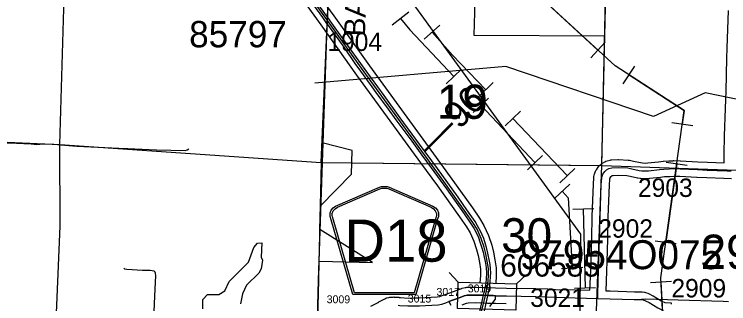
# Model space of a CAD drawing. Extents: x -157.2 to -99.3, y 12.2 to 46.2.
# Drawn here: x -145.747 to -143.029, y 36.628 to 37.727 of the extents above; entities that cross this region are included whole.
import ezdxf

# ---------------------------------------------------------------- set-up
doc = ezdxf.new("R2010")
doc.units = 0
for name, color, linetype in [('tdCoCityStreetMinor', 7, 'Continuous'), ('tdCoCorpBndry', 7, 'Continuous'), ('tdCoCorpPopTxt', 7, 'Continuous'), ('tdCoDivCarto', 7, 'Continuous'), ('tdCoHydroRiver', 7, 'Continuous'), ('tdCoPipe', 7, 'Continuous'), ('tdCoPipe1', 7, 'Continuous'), ('tdCoPipe2', 7, 'Continuous'), ('tdCoPriCL', 7, 'Continuous'), ('tdCoPriDiv', 7, 'Continuous'), ('tdCoSecRdNmbr', 7, 'Continuous'), ('tdCoSecRdTxt', 7, 'Continuous'), ('tdCoSecRteBand', 7, 'Continuous'), ('tdCoSecRteCL', 7, 'Continuous'), ('tdCoSectLine', 7, 'Continuous'), ('tdCoSectLinePart', 7, 'Continuous'), ('tdCoSectNmbr', 7, 'Continuous'), ('tdCoShieldCoRteHrd', 7, 'Continuous'), ('tdCoStrucNonDivPri', 7, 'Continuous'), ('tdCoStrucPriMaintName', 7, 'Continuous'), ('tdCoStrucSecFHWANum', 7, 'Continuous'), ('tdCoSurfAsphalt', 7, 'Continuous'), ('tdCoSurfGravel', 7, 'Continuous'), ('tdCoSurfLNO', 7, 'Continuous'), ('tdCoTwpBndry', 7, 'Continuous'), ('tdStHwyPriRefPost1', 7, 'Continuous')]:
    doc.layers.add(name, color=color, linetype=linetype)

msp = doc.modelspace()

# ---------------------------------------------------------------- linework, layer by layer
at = {"layer": 'tdCoCityStreetMinor'}
for points in [[(-146.0712, 37.2523), (-146.0597, 37.253), (-146.0068, 37.2504), (-145.9695, 37.2485), (-145.8817, 37.2441), (-145.8233, 37.2411), (-145.8193, 37.2409), (-145.7377, 37.2377), (-145.6822, 37.2347), (-145.6612, 37.2332), (-145.6373, 37.2347), (-145.5966, 37.2335), (-145.5697, 37.232), (-145.5083, 37.2261), (-145.4028, 37.2217), (-145.3228, 37.2181)], [(-145.3228, 37.2181), (-145.3152, 37.2177), (-145.2062, 37.2125), (-145.0957, 37.2106), (-145.0888, 37.2125), (-145.0827, 37.2162)], [(-145.3295, 36.7634), (-145.3271, 36.7609), (-145.3192, 36.7589), (-145.2587, 36.7552), (-145.2301, 36.7555), (-145.2225, 36.7545), (-145.2163, 36.7528), (-145.2119, 36.7491), (-145.2114, 36.7479)], [(-145.2263, 36.2821), (-145.2252, 36.3091), (-145.223, 36.3986), (-145.2205, 36.4882), (-145.2173, 36.5417), (-145.2102, 36.6845), (-145.2084, 36.734), (-145.2094, 36.7434), (-145.2114, 36.7479)]]:
    msp.add_lwpolyline(points, dxfattribs=at)
at = {"layer": 'tdCoCorpBndry'}
for points in [[(-143.9908, 37.9076), (-143.9989, 37.6487), (-143.5002, 37.6452), (-143.4894, 38.1369)], [(-144.5957, 36.4338), (-144.5873, 36.79), (-144.3834, 36.7845), (-144.5845, 36.9098), (-144.5823, 37), (-144.4643, 37.1202), (-144.4611, 37.2101), (-144.5753, 37.2385), (-144.5551, 37.7042), (-144.5517, 37.7829)], [(-143.9379, 36.6172), (-143.9166, 36.6446), (-143.9163, 36.6584), (-143.925, 36.6586), (-143.9455, 36.6591), (-143.9537, 36.6594), (-143.9628, 36.6598), (-143.9823, 36.6603), (-143.9909, 36.6606), (-144.0242, 36.6601), (-144.0353, 36.6574), (-144.0548, 36.65), (-144.0932, 36.6357), (-144.0861, 36.6222)]]:
    msp.add_lwpolyline(points, dxfattribs=at)
at = {"layer": 'tdCoDivCarto'}
for points in [[(-144.5549, 37.7164), (-144.5986, 37.7758), (-144.6594, 37.8612)], [(-144.5549, 37.7164), (-144.5986, 37.7758), (-144.6594, 37.8612)], [(-144.6082, 37.7617), (-144.5743, 37.715), (-144.5559, 37.6892)], [(-144.6082, 37.7617), (-144.5743, 37.715), (-144.5559, 37.6892)], [(-144.5545, 37.7158), (-144.5549, 37.7164)], [(-144.5545, 37.7158), (-144.5549, 37.7164)], [(-143.9455, 36.6591), (-143.9408, 36.681), (-143.9377, 36.6975), (-143.9358, 36.7109), (-143.9346, 36.7312), (-143.9343, 36.7451), (-143.9348, 36.7602), (-143.937, 36.7771), (-143.9386, 36.7896), (-143.9449, 36.8204), (-143.9501, 36.8419), (-143.9537, 36.8536), (-143.9609, 36.8758), (-143.9731, 36.9031), (-143.9841, 36.9239), (-143.9941, 36.9401), (-144.0252, 36.9846), (-144.0584, 37.0327), (-144.1368, 37.1414), (-144.2056, 37.2342), (-144.2788, 37.3336), (-144.3397, 37.4192), (-144.4117, 37.5172), (-144.4774, 37.6095), (-144.5322, 37.6855), (-144.5545, 37.7158)], [(-143.9455, 36.6591), (-143.9408, 36.681), (-143.9377, 36.6975), (-143.9358, 36.7109), (-143.9346, 36.7312), (-143.9343, 36.7451), (-143.9348, 36.7602), (-143.937, 36.7771), (-143.9386, 36.7896), (-143.9449, 36.8204), (-143.9501, 36.8419), (-143.9537, 36.8536), (-143.9609, 36.8758), (-143.9731, 36.9031), (-143.9841, 36.9239), (-143.9941, 36.9401), (-144.0252, 36.9846), (-144.0584, 37.0327), (-144.1368, 37.1414), (-144.2056, 37.2342), (-144.2788, 37.3336), (-144.3397, 37.4192), (-144.4117, 37.5172), (-144.4774, 37.6095), (-144.5322, 37.6855), (-144.5545, 37.7158)], [(-144.5559, 37.6892), (-144.5556, 37.6889)], [(-144.5559, 37.6892), (-144.5556, 37.6889)], [(-144.5556, 37.6889), (-144.4937, 37.6023), (-144.4508, 37.5411), (-144.4293, 37.5115), (-144.3862, 37.4516), (-144.3711, 37.4309), (-144.3247, 37.3675), (-144.2954, 37.3268), (-144.235, 37.2452), (-144.196, 37.1917), (-144.1605, 37.1438), (-144.103, 37.0644), (-144.0352, 36.9692), (-144.0113, 36.9345), (-143.999, 36.9147), (-143.9926, 36.9029), (-143.9812, 36.8792), (-143.9751, 36.8634), (-143.9677, 36.8403), (-143.963, 36.824), (-143.9588, 36.8045), (-143.9556, 36.7882), (-143.9521, 36.765), (-143.9506, 36.7443), (-143.9514, 36.7239), (-143.9534, 36.7054), (-143.9595, 36.6753), (-143.9628, 36.6598)], [(-144.5556, 37.6889), (-144.4937, 37.6023), (-144.4508, 37.5411), (-144.4293, 37.5115), (-144.3862, 37.4516), (-144.3711, 37.4309), (-144.3247, 37.3675), (-144.2954, 37.3268), (-144.235, 37.2452), (-144.196, 37.1917), (-144.1605, 37.1438), (-144.103, 37.0644), (-144.0352, 36.9692), (-144.0113, 36.9345), (-143.999, 36.9147), (-143.9926, 36.9029), (-143.9812, 36.8792), (-143.9751, 36.8634), (-143.9677, 36.8403), (-143.963, 36.824), (-143.9588, 36.8045), (-143.9556, 36.7882), (-143.9521, 36.765), (-143.9506, 36.7443), (-143.9514, 36.7239), (-143.9534, 36.7054), (-143.9595, 36.6753), (-143.9628, 36.6598)], [(-143.9628, 36.6598), (-143.9726, 36.6144), (-143.9847, 36.5638), (-144.017, 36.4363), (-144.0481, 36.3133), (-144.0702, 36.238), (-144.0804, 36.1973), (-144.0881, 36.1648), (-144.0882, 36.1644)], [(-143.9628, 36.6598), (-143.9726, 36.6144), (-143.9847, 36.5638), (-144.017, 36.4363), (-144.0481, 36.3133), (-144.0702, 36.238), (-144.0804, 36.1973), (-144.0881, 36.1648), (-144.0882, 36.1644)], [(-144.0708, 36.1641), (-144.0627, 36.1994), (-144.0584, 36.2166), (-144.0441, 36.2673), (-144.0204, 36.3555), (-143.9898, 36.4757), (-143.9721, 36.5448), (-143.957, 36.6062), (-143.9532, 36.6232), (-143.9482, 36.6464), (-143.9455, 36.6591)], [(-144.0708, 36.1641), (-144.0627, 36.1994), (-144.0584, 36.2166), (-144.0441, 36.2673), (-144.0204, 36.3555), (-143.9898, 36.4757), (-143.9721, 36.5448), (-143.957, 36.6062), (-143.9532, 36.6232), (-143.9482, 36.6464), (-143.9455, 36.6591)]]:
    msp.add_lwpolyline(points, dxfattribs=at)
at = {"layer": 'tdCoHydroRiver'}
msp.add_lwpolyline([(-145.0289, 36.6078), (-145.0293, 36.6442), (-145.0114, 36.6625), (-144.9687, 36.6627), (-144.9462, 36.6762), (-144.9292, 36.7119), (-144.8558, 36.7853), (-144.835, 36.8415), (-144.8219, 36.8584), (-144.8045, 36.8594), (-144.8078, 36.8043), (-144.8019, 36.793), (-144.8077, 36.7601), (-144.8161, 36.7445), (-144.8634, 36.6987), (-144.8787, 36.666), (-144.8862, 36.6268)], dxfattribs=at)
at = {"layer": 'tdCoPipe'}
for p, q in [((-143.5538, 37.5619), (-143.4992, 37.6212)), ((-143.43, 37.4632), (-143.3862, 37.5307)), ((-143.2456, 37.3161), (-143.1658, 37.3049)), ((-143.2667, 37.1655), (-143.1871, 37.1543)), ((-143.3086, 36.8674), (-143.2288, 36.8562)), ((-143.3271, 36.709), (-143.2468, 36.7133))]:
    msp.add_line(p, q, dxfattribs=at)
for points in [[(-143.6986, 32.0013), (-143.8537, 32.158), (-143.9767, 32.8002), (-143.9699, 34.5789), (-143.6225, 35.3891), (-143.4712, 35.4798), (-143.4387, 35.9175), (-143.2567, 36.1488), (-143.2877, 36.7262), (-143.1986, 37.3614), (-143.4614, 37.5316), (-143.9241, 37.9577), (-144.2011, 38.3657), (-144.4708, 38.931)], [(-144.5317, 38.1832), (-143.5928, 36.8918), (-143.6099, 34.8602), (-143.4402, 34.5415), (-143.5694, 34.3304), (-143.5634, 33.7239), (-143.4667, 33.4993), (-143.5656, 33.4168), (-143.4755, 33.1706), (-143.455, 32.2186), (-143.5122, 31.3968), (-143.6938, 30.9939), (-143.6811, 29.9265), (-143.7347, 27.6406), (-143.7362, 26.8708), (-143.9217, 26.7732), (-143.8183, 26.5085), (-143.8116, 26.1034), (-144.0839, 25.9289), (-143.0557, 24.1836)], [(-143.7479, 37.7954), (-143.5265, 37.5915)], [(-141.4768, 37.6316), (-142.3456, 37.409), (-142.8158, 37.3667), (-143.1182, 37.4285), (-143.3155, 37.3393), (-143.8762, 37.5293), (-144.6035, 37.4656)], [(-143.4081, 37.497), (-143.1986, 37.3614), (-143.2057, 37.3105)], [(-143.2269, 37.1599), (-143.2687, 36.8618)], [(-143.2869, 36.7112), (-143.2708, 36.4106)]]:
    msp.add_lwpolyline(points, dxfattribs=at)
at = {"layer": 'tdCoPipe1'}
for p, q in [((-144.1873, 37.6336), (-144.1274, 37.6868)), ((-143.9824, 37.4126), (-143.9244, 37.4679)), ((-143.879, 37.304), (-143.8209, 37.3593)), ((-143.672, 37.0868), (-143.614, 37.1422)), ((-143.6225, 36.9871), (-143.5424, 36.989)), ((-143.6154, 36.6872), (-143.5352, 36.6891))]:
    msp.add_line(p, q, dxfattribs=at)
for points in [[(-144.1574, 37.6602), (-144.0792, 37.5723), (-143.9534, 37.4403)], [(-143.8499, 37.3317), (-143.643, 37.1145)], [(-143.5825, 36.9881), (-143.5753, 36.6882)]]:
    msp.add_lwpolyline(points, dxfattribs=at)
at = {"layer": 'tdCoPipe2'}
for p, q in [((-144.3089, 37.6869), (-144.2462, 37.7369)), ((-144.1042, 37.4633), (-144.0459, 37.5184)), ((-144.0011, 37.3543), (-143.9429, 37.4094)), ((-143.795, 37.1363), (-143.7367, 37.1914)), ((-143.6919, 37.0274), (-143.6337, 37.0824)), ((-143.6646, 36.7621), (-143.5845, 36.7667))]:
    msp.add_line(p, q, dxfattribs=at)
for points in [[(-144.2776, 37.7119), (-144.2424, 37.6679), (-144.075, 37.4909)], [(-143.972, 37.3819), (-143.7659, 37.1639)], [(-143.6628, 37.0549), (-143.6398, 37.0306), (-143.6245, 36.7644)]]:
    msp.add_lwpolyline(points, dxfattribs=at)
at = {"layer": 'tdCoPriCL'}
msp.add_lwpolyline([(-144.01, 36.4314), (-143.9541, 36.6594), (-143.9453, 36.7025), (-143.9431, 36.7334), (-143.9431, 36.7621), (-143.9478, 36.7898), (-143.9529, 36.8173), (-143.9594, 36.8424), (-143.9704, 36.8759), (-143.9864, 36.9109), (-144.0018, 36.936), (-144.0288, 36.9749), (-144.1127, 37.0927), (-144.1767, 37.1802), (-144.42, 37.5138), (-144.5556, 37.7044), (-144.6009, 37.7672)], dxfattribs=at)
at = {"layer": 'tdCoPriDiv'}
for points in [[(-144.6772, 37.8219), (-144.58, 37.6869), (-144.4444, 37.4963), (-144.2009, 37.1625), (-144.1371, 37.0752), (-144.0533, 36.9576), (-144.0269, 36.9196), (-144.013, 36.8968), (-143.9984, 36.865), (-143.9882, 36.8339), (-143.9822, 36.8108), (-143.9773, 36.7846), (-143.9731, 36.7596), (-143.9731, 36.7345), (-143.9751, 36.7074)], [(-144.5765, 37.7848), (-144.5312, 37.7219), (-144.3957, 37.5314), (-144.1525, 37.1979), (-144.0884, 37.1103), (-144.0042, 36.9922), (-143.9766, 36.9524), (-143.9599, 36.9251), (-143.9424, 36.8869), (-143.9306, 36.8508), (-143.9236, 36.8239), (-143.9182, 36.795), (-143.9131, 36.7646), (-143.9131, 36.7324), (-143.9153, 36.7058)]]:
    msp.add_lwpolyline(points, dxfattribs=at)
at = {"layer": 'tdCoSecRteBand'}
for points in [[(-144.3898, 36.6181), (-144.3601, 36.6343), (-144.3601, 36.6343), (-144.36, 36.6344), (-144.337, 36.6469), (-144.3337, 36.6487), (-144.3301, 36.6497), (-144.3215, 36.6519), (-144.3185, 36.6527), (-144.3154, 36.6528), (-144.3053, 36.6533), (-144.3035, 36.6534), (-144.3017, 36.6533), (-144.2854, 36.6521), (-144.2842, 36.6521), (-144.2832, 36.6519), (-144.2776, 36.6515), (-144.2775, 36.6515), (-144.2775, 36.6515), (-144.2484, 36.6494), (-144.2271, 36.6496), (-144.2064, 36.6504), (-144.1838, 36.6513), (-144.1376, 36.6539), (-144.128, 36.6557), (-144.1146, 36.6597), (-144.1036, 36.6638), (-144.0654, 36.678), (-144.0485, 36.6844), (-144.046, 36.6854), (-144.0442, 36.6861), (-144.0424, 36.6865), (-144.0313, 36.6892), (-144.0281, 36.69), (-144.0247, 36.6901), (-143.9914, 36.6906), (-143.9907, 36.6906), (-143.9901, 36.6906), (-143.962, 36.6898), (-143.9618, 36.6898), (-143.9617, 36.6898), (-143.9445, 36.6891), (-143.916, 36.6884), (-143.9156, 36.6884), (-143.8737, 36.6874), (-143.7626, 36.6856), (-143.7624, 36.6856), (-143.7622, 36.6856), (-143.7186, 36.6844), (-143.7179, 36.6844), (-143.7172, 36.6843), (-143.6879, 36.6822), (-143.6127, 36.6805), (-143.6126, 36.6805), (-143.6125, 36.6804), (-143.5567, 36.6789), (-143.5537, 36.7544), (-143.5525, 36.7902), (-143.55, 36.8751), (-143.5483, 36.9598), (-143.5483, 36.96), (-143.5483, 36.9603), (-143.5436, 37.0807), (-143.5436, 37.0811), (-143.5436, 37.0816), (-143.5418, 37.1067), (-143.5417, 37.108), (-143.5415, 37.1093), (-143.5403, 37.1172), (-143.5398, 37.1205), (-143.5385, 37.1237), (-143.5356, 37.1311), (-143.5343, 37.1341), (-143.5325, 37.1369), (-143.5256, 37.147), (-143.5235, 37.15), (-143.5208, 37.1524), (-143.5139, 37.1586), (-143.5116, 37.1606), (-143.509, 37.1621), (-143.5001, 37.1673), (-143.4962, 37.1696), (-143.4917, 37.1706), (-143.4799, 37.1734), (-143.4773, 37.1739), (-143.4747, 37.1741), (-143.4505, 37.1753), (-143.4491, 37.1754), (-143.4476, 37.1753), (-143.4116, 37.1736), (-143.4092, 37.1735), (-143.4069, 37.173), (-143.3914, 37.1698), (-143.3913, 37.1698), (-143.3912, 37.1697), (-143.3643, 37.164), (-143.3563, 37.1627), (-143.3464, 37.1623), (-143.3361, 37.1627), (-143.2956, 37.1673), (-143.2789, 37.1692), (-143.2779, 37.1693), (-143.2769, 37.1694), (-143.2568, 37.1704), (-143.2404, 37.1713), (-143.2391, 37.1714), (-143.2378, 37.1714), (-143.2133, 37.1706), (-143.2131, 37.1706), (-143.2128, 37.1706), (-143.1467, 37.1674), (-143.1095, 37.1657), (-143.0467, 37.1637), (-143.0461, 37.1984), (-143.0461, 37.1985), (-143.0461, 37.1986), (-143.0447, 37.2649), (-143.0447, 37.2651), (-143.0447, 37.2653), (-143.0412, 37.3701), (-143.0412, 37.3702), (-143.0412, 37.3704), (-143.0382, 37.4359), (-143.0355, 37.5606), (-143.0355, 37.5607), (-143.0355, 37.5607), (-143.0346, 37.5982), (-143.0345, 37.5983), (-143.0345, 37.5984), (-143.0301, 37.7417)], [(-143.0182, 37.1025), (-143.0478, 37.103), (-143.0478, 37.1037), (-143.1116, 37.1057), (-143.1118, 37.1058), (-143.1121, 37.1058), (-143.1495, 37.1075), (-143.1496, 37.1075), (-143.1496, 37.1075), (-143.2154, 37.1107), (-143.2382, 37.1114), (-143.2534, 37.1105), (-143.2536, 37.1105), (-143.2537, 37.1105), (-143.2729, 37.1095), (-143.2887, 37.1077), (-143.2887, 37.1077), (-143.2888, 37.1076), (-143.3305, 37.103), (-143.3316, 37.1028), (-143.3327, 37.1028), (-143.3453, 37.1023), (-143.3464, 37.1023), (-143.3476, 37.1023), (-143.3604, 37.1028), (-143.3622, 37.1029), (-143.3641, 37.1032), (-143.3747, 37.1049), (-143.3754, 37.105), (-143.3761, 37.1052), (-143.4037, 37.1111), (-143.4168, 37.1138), (-143.449, 37.1153), (-143.469, 37.1143), (-143.4739, 37.1132), (-143.4762, 37.1118), (-143.4781, 37.1101), (-143.4811, 37.1057), (-143.4816, 37.1046), (-143.4821, 37.1013), (-143.4837, 37.0779), (-143.4883, 36.9583), (-143.49, 36.8737), (-143.49, 36.8736), (-143.4901, 36.8735), (-143.4925, 36.7884), (-143.4925, 36.7883), (-143.4925, 36.7882), (-143.4938, 36.7522), (-143.4938, 36.7521), (-143.4938, 36.7521), (-143.4967, 36.6772), (-143.4956, 36.6772), (-143.4796, 36.6767), (-143.4795, 36.6767), (-143.4794, 36.6767), (-143.3873, 36.6736), (-143.3686, 36.6734), (-143.3623, 36.6733), (-143.3602, 36.6733), (-143.3581, 36.673), (-143.3499, 36.6717), (-143.3478, 36.6714), (-143.3457, 36.6708), (-143.3368, 36.6681), (-143.334, 36.6672), (-143.3314, 36.6658), (-143.3176, 36.6584), (-143.3169, 36.6581), (-143.3163, 36.6577), (-143.2836, 36.6381), (-143.2723, 36.632), (-143.2476, 36.6309), (-143.2478, 36.6258)], [(-143.875, 36.6274), (-143.9167, 36.6284), (-143.9171, 36.6284), (-143.9462, 36.6291), (-143.9464, 36.6291), (-143.9467, 36.6291), (-143.9639, 36.6298), (-143.9911, 36.6306), (-144.0204, 36.6301), (-144.0264, 36.6287), (-144.0272, 36.6284), (-144.0442, 36.6219)]]:
    msp.add_lwpolyline(points, dxfattribs=at)
at = {"layer": 'tdCoSecRteCL'}
for points in [[(-143.5264, 36.648), (-143.5272, 36.6662), (-143.5237, 36.7532), (-143.5225, 36.7892), (-143.52, 36.8743), (-143.5183, 36.9592), (-143.5136, 37.0795), (-143.5119, 37.1047), (-143.5107, 37.1125), (-143.5077, 37.1199), (-143.5008, 37.1301), (-143.4939, 37.1362), (-143.485, 37.1414), (-143.4732, 37.1441), (-143.449, 37.1453), (-143.413, 37.1436), (-143.3975, 37.1404), (-143.3699, 37.1345), (-143.3593, 37.1328), (-143.3464, 37.1323), (-143.3339, 37.1328), (-143.2922, 37.1375), (-143.2754, 37.1394), (-143.2552, 37.1404), (-143.2387, 37.1414), (-143.2142, 37.1407), (-143.1482, 37.1375), (-143.1107, 37.1357), (-143.0345, 37.1333), (-143.0193, 37.1326)], [(-144.1209, 36.6265), (-144.1051, 36.6312), (-144.0932, 36.6357), (-144.0548, 36.65), (-144.0379, 36.6564), (-144.0353, 36.6574), (-144.0242, 36.6601), (-143.9909, 36.6606), (-143.9628, 36.6598), (-143.9455, 36.6591), (-143.9163, 36.6584), (-143.9163, 36.6584), (-143.8743, 36.6574), (-143.7631, 36.6556), (-143.7194, 36.6544), (-143.6893, 36.6522), (-143.6134, 36.6505), (-143.5264, 36.648)], [(-143.5264, 36.648), (-143.4805, 36.6468), (-143.388, 36.6436), (-143.3689, 36.6434), (-143.3626, 36.6433), (-143.3544, 36.6421), (-143.3456, 36.6394), (-143.3318, 36.632), (-143.2985, 36.612), (-143.2814, 36.6029), (-143.2789, 36.6023)]]:
    msp.add_lwpolyline(points, dxfattribs=at)
at = {"layer": 'tdCoSectLine'}
for points in [[(-145.5734, 37.2322), (-145.5448, 38.2239)], [(-144.5788, 37.1648), (-144.5359, 38.1566)], [(-143.5114, 37.1535), (-143.4897, 38.1369)], [(-146.5753, 37.2765), (-145.5734, 37.2322)], [(-145.601, 36.2327), (-145.5728, 36.9221), (-145.5734, 37.2322)], [(-145.5734, 37.2322), (-144.5788, 37.1648)], [(-144.5788, 37.1648), (-144.6022, 36.1771)], [(-144.5788, 37.1648), (-143.5114, 37.1535)], [(-143.5489, 36.151), (-143.5114, 37.1535)], [(-143.5114, 37.1535), (-142.5224, 37.1194)]]:
    msp.add_lwpolyline(points, dxfattribs=at)
at = {"layer": 'tdCoSectLinePart'}
for points in [[(-144.558, 37.6465), (-144.5527, 37.7674)], [(-143.5113, 37.1602), (-143.5006, 37.6452)], [(-144.4631, 37.1636), (-143.5187, 37.1536)], [(-144.5894, 36.7171), (-144.5952, 36.4744)]]:
    msp.add_lwpolyline(points, dxfattribs=at)
at = {"layer": 'tdCoShieldCoRteHrd'}
for points in [[(-144.4589, 36.6634), (-144.5408, 36.9463), (-144.5447, 36.9594), (-144.5454, 36.9653), (-144.5454, 36.9731), (-144.5412, 36.9835), (-144.5339, 36.9919), (-144.5243, 36.9986), (-144.3571, 37.071), (-144.3495, 37.0726), (-144.3391, 37.0735), (-144.3287, 37.0726), (-144.3212, 37.071), (-144.1539, 36.9986), (-144.1443, 36.9919), (-144.137, 36.9835), (-144.1328, 36.9731), (-144.1328, 36.9653), (-144.1335, 36.9594), (-144.1374, 36.9463), (-144.2194, 36.6634)], [(-144.453, 36.6697), (-144.5327, 36.945), (-144.5365, 36.9576), (-144.5372, 36.9633), (-144.5372, 36.9708), (-144.5331, 36.9807), (-144.5261, 36.9888), (-144.5169, 36.9952), (-144.3563, 37.0647), (-144.3491, 37.0663), (-144.3391, 37.0671), (-144.3291, 37.0663), (-144.3219, 37.0647), (-144.1613, 36.9952), (-144.1521, 36.9888), (-144.1451, 36.9807), (-144.1411, 36.9708), (-144.1411, 36.9633), (-144.1418, 36.9576), (-144.1455, 36.945), (-144.2252, 36.6697)]]:
    msp.add_lwpolyline(points, close=True, dxfattribs=at)
at = {"layer": 'tdCoStrucNonDivPri'}
for p, q in [((-144.0576, 36.7098), (-144.0919, 36.7461)), ((-143.836, 36.7034), (-143.7996, 36.7378))]:
    msp.add_line(p, q, dxfattribs=at)
msp.add_lwpolyline([(-144.0576, 36.7098), (-143.836, 36.7034), (-143.8389, 36.6035), (-144.0605, 36.6098)], close=True, dxfattribs=at)
at = {"layer": 'tdCoSurfAsphalt'}
for points in [[(-144.2865, 36.6221), (-144.2797, 36.6216), (-144.2494, 36.6194), (-144.2264, 36.6196), (-144.2052, 36.6204), (-144.1823, 36.6214), (-144.134, 36.6241), (-144.1209, 36.6265), (-144.1051, 36.6312), (-144.0932, 36.6357), (-144.0932, 36.6357)], [(-144.0932, 36.6357), (-144.0548, 36.65), (-144.0379, 36.6564)], [(-144.0379, 36.6564), (-144.0353, 36.6574), (-144.0242, 36.6601), (-143.9909, 36.6606), (-143.9628, 36.6598), (-143.9455, 36.6591), (-143.9163, 36.6584), (-143.9163, 36.6584)], [(-143.9163, 36.6584), (-143.8743, 36.6574), (-143.7631, 36.6556), (-143.7194, 36.6544), (-143.6893, 36.6522), (-143.6134, 36.6505), (-143.5264, 36.648)], [(-143.5264, 36.648), (-143.4805, 36.6468), (-143.388, 36.6436), (-143.3689, 36.6434), (-143.3626, 36.6433), (-143.3544, 36.6421), (-143.3456, 36.6394), (-143.3318, 36.632), (-143.2985, 36.612), (-143.2814, 36.6029), (-143.2789, 36.6023)]]:
    msp.add_lwpolyline(points, dxfattribs=at)
at = {"layer": 'tdCoSurfGravel'}
msp.add_lwpolyline([(-143.5264, 36.648), (-143.5272, 36.6662), (-143.5237, 36.7532), (-143.5225, 36.7892), (-143.52, 36.8743), (-143.5183, 36.9592), (-143.5136, 37.0795), (-143.5119, 37.1047), (-143.5107, 37.1125), (-143.5077, 37.1199), (-143.5008, 37.1301), (-143.4939, 37.1362), (-143.485, 37.1414), (-143.4732, 37.1441), (-143.449, 37.1453), (-143.413, 37.1436), (-143.3975, 37.1404), (-143.3699, 37.1345), (-143.3593, 37.1328), (-143.3464, 37.1323), (-143.3339, 37.1328), (-143.2922, 37.1375), (-143.2754, 37.1394), (-143.2552, 37.1404), (-143.2387, 37.1414), (-143.2142, 37.1407), (-143.1482, 37.1375), (-143.1107, 37.1357), (-143.0345, 37.1333), (-143.0193, 37.1326)], dxfattribs=at)
at = {"layer": 'tdCoSurfLNO'}
msp.add_lwpolyline([(-143.3689, 36.6434), (-143.3601, 36.6455), (-143.3445, 36.6468), (-143.2212, 36.6431), (-143.0501, 36.6374), (-143.0296, 36.6362)], dxfattribs=at)
at = {"layer": 'tdCoTwpBndry'}
msp.add_lwpolyline([(-144.5952, 36.4739), (-144.5894, 36.7171), (-144.558, 37.6465), (-144.5527, 37.7674)], dxfattribs=at)

# ---------------------------------------------------------------- texts
at = {"layer": 'tdCoCorpPopTxt'}
msp.add_text('85797', height=0.1, dxfattribs=at).set_placement((-145.0815, 37.602))
at = {"layer": 'tdCoSecRdNmbr'}
for s, height, rotation, p in [('1904', 0.07, 359.8897, (-144.5559, 37.5884)), ('2903', 0.07, 359.8906, (-143.3743, 37.0339)), ('2902', 0.07, 359.8906, (-143.5253, 36.8789)), ('2909', 0.07, 359.8897, (-143.2471, 36.6519)), ('3019', 0.03, 359.8897, (-144.0216, 36.6711)), ('3015', 0.03, 359.8897, (-144.2499, 36.6324)), ('3017', 0.03, 359.8897, (-144.1406, 36.6578)), ('3021', 0.07, 359.8897, (-143.7841, 36.6157)), ('3009', 0.03, 359.8897, (-144.5584, 36.6297))]:
    msp.add_text(s, height=height, rotation=rotation, dxfattribs=at).set_placement(p)
at = {"layer": 'tdCoSecRdTxt'}
msp.add_text('BARKER', height=0.08, rotation=88.1015, dxfattribs=at).set_placement((-144.4127, 37.6428))
at = {"layer": 'tdCoSectNmbr'}
for s, rotation, p in [('19', 359.89, (-144.1389, 37.3305)), ('30', 359.8901, (-143.8945, 36.8228)), ('29', 359.8908, (-143.1356, 36.7604))]:
    msp.add_text(s, height=0.13, rotation=rotation, dxfattribs=at).set_placement(p)
at = {"layer": 'tdCoShieldCoRteHrd'}
msp.add_text('D18', height=0.16, dxfattribs=at).set_placement((-144.491, 36.7876))
at = {"layer": 'tdCoStrucPriMaintName'}
msp.add_text('97954O075', height=0.11, dxfattribs=at).set_placement((-143.8233, 36.7591))
at = {"layer": 'tdCoStrucSecFHWANum'}
msp.add_text('606585', height=0.085, dxfattribs=at).set_placement((-143.8981, 36.7309))
at = {"layer": 'tdStHwyPriRefPost1'}
msp.add_text('‒‒96', height=0.1, rotation=45, dxfattribs=at).set_placement((-144.1585, 37.1824))

doc.saveas('drawing.dxf')
